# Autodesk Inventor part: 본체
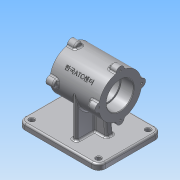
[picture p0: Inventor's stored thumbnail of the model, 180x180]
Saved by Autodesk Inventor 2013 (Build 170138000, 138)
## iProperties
Created: 2015-12
Part Number: 본체
Material: 알루미늄 6061
Document SubType Name: Modeling
Designer: Administrator
Density: 2.71 g/cm^3
Mass: 1164.59 g
Surface Area: 814.915 cm^2
Volume: 429.737 cm^3
Author: Administrator
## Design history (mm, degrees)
sketch "스케치1"
  geometry: L1 (-80, 55)-(60, 55); L2 (60, 55)-(60, -55); L3 (60, -55)-(-80, -55); L4 (-80, -55)-(-80, 55); 2 further points
  constraints: 8 end point, 2 parallel, 1 horizontal, 1 horizontal alignment, 1 midpoint, 1 perpendicular
  dimensions: "d0" = 140 distance of L1.start L1.end; "d2" = 110 distance of L3.end L1.start; "d3" = 80 distance from line of L4 point (0, 0)
extrude "돌출1" new body sketch "스케치1" distance "d4" = 10; taper "d5" = 0 deg
sketch "스케치5"
  geometry: L1 (-37, 80)-(-37, 0); L2 (37, 80)-(37, 0); L3 (-37, 80)-(37, 80); L4 (-37, 0)-(37, 0); A1 r 37 centre (0, 80) between (-37, 80) and (37, 80); 1 further point
  constraints: 8 end point, 2 parallel, 2 point on circle, 2 tangent, 1 centre point, 1 perpendicular, 1 vertical, 1 vertical alignment
  dimensions: "d30" = 74 diameter of A1; "d32" = 80 distance of point (0, 0) A1.centre
extrude "돌출4" join sketch "스케치5" stored distance "d33" = 85; taper "d34" = 0 deg
extrude "돌출5" join sketch "스케치5" stored distance "d35" = 8; taper "d36" = 0 deg
node "작업 평면2"
sketch "스케치7"
  geometry: L1 (80, 10)-(-60, 10) reference; L2 (-25, 10)-(-16.405, 80); L3 (-16.405, 80)-(16.405, 80); L4 (16.405, 80)-(25, 10); L5 (-60, 0)-(80, 0) reference; L6 (-25, 10)-(25, 10); 1 further point
  constraints: 8 end point, 2 point on line, 1 collinear, 1 parallel
  dimensions: "d40" = 25 horizontal distance of point (0, 0) L2.start; "d41" = 50 distance of L4.end L2.start; "d42" = 97 deg angle of L2 L1; "d43" = 97 deg angle of L4 L1; "d44" = 80 distance between parallel lines of L5 L3
extrude "돌출6" join sketch "스케치7" stored distance "d45" = 12; taper "d46" = 0 deg
sketch "스케치9"
  geometry: L1 (-80, 55)-(60, 55) reference; L2 (60, 55)-(60, -55) reference; L3 (60, -55)-(-80, -55) reference; L4 (-80, -55)-(-80, 55) reference; 5 further points
  constraints: 2 horizontal alignment, 2 vertical alignment
  dimensions: "d54" = 116 distance of point (48, 43) point (-68, 43); "d56" = 12 distance from line of L1 point (-68, 43); "d57" = 12 distance from line of point (-68, 43) L4; "d58" = 86 distance of point (-68, -43) point (-68, 43)
hole "구멍1" sketch "스케치9" at (-68, 43), (48, 43), (48, -43), (-68, -43) diameter "d59" = 8; stored, may be unused: countersink angle "d63" = 90 deg, drill point angle "d65" = 118 deg; dims "d60" = 6, "d61" = 4, "d62" = 2, "d64" = 8
fillet "모깎기1" dims "d66" = 12
node "작업 평면4"
sketch "스케치12"
  geometry: L1 (-23.753, 109.765)-(23.753, 109.765); L2 (23.753, 109.765)-(23.753, 102.561); L3 (23.753, 102.561)-(-23.753, 102.561); L4 (-23.753, 102.561)-(-23.753, 109.765); L5 (-42.5, 117)-(-42.5, 43) reference; 4 further points
  constraints: 2 midpoint, 1 horizontal alignment, 1 vertical alignment, 2 other
  dimensions: "d71" = 42.5 distance from line of point (0, 106.163) L5; "d72" = 106.163 distance of point (0, 0) point (0, 106.163)
feature "엠보싱1" sketch "스케치12" dims "d73" = 0.5, "d74" = 0
sketch "스케치18"
  geometry: L1 (-17.479, 105.93)-(-20.955, 105.93) reference; L2 (-20.955, 105.93)-(-20.955, 105.609) reference; L3 (-20.955, 105.609)-(-18.016, 105.609) reference; L4 (-18.016, 105.609)-(-18.016, 104.574) reference; L5 (-18.016, 104.574)-(-20.638, 104.574) reference; L6 (-20.638, 104.574)-(-20.638, 104.237) reference; L7 (-20.638, 104.237)-(-18.016, 104.237) reference; L8 (-18.016, 104.237)-(-18.016, 103.028) reference; L9 (-17.479, 102.651)-(-17.479, 105.93) reference; L10 (-11.764, 105.248)-(-13.001, 105.248) reference; L11 (-13.001, 105.248)-(-13.001, 106.527) reference; L12 (-13.001, 106.527)-(-13.449, 106.527) reference; L13 (-13.547, 106.328)-(-13.547, 102.721) reference; L14 (-13.547, 102.721)-(-13.001, 102.721) reference; L15 (-13.001, 102.721)-(-13.001, 104.943) reference; L16 (-13.001, 104.943)-(-11.764, 104.943) reference; L17 (-11.764, 104.943)-(-11.764, 105.248) reference; L18 (-10.404, 106.368)-(-10.885, 106.368) reference; L19 (0.586, 101.567)-(0.586, 105.784) reference; L20 (0.586, 105.784)-(2.45, 105.784) reference; L21 (2.45, 105.784)-(2.45, 106.138) reference; L22 (2.45, 106.138)-(-1.832, 106.138) reference; L23 (-1.832, 106.138)-(-1.832, 105.784) reference; L24 (-1.832, 105.784)-(0.041, 105.784) reference; L25 (0.041, 105.784)-(0.041, 101.567) reference; L26 (0.041, 101.567)-(0.586, 101.567) reference; L27 (5.853, 106.138)-(5.202, 106.138) reference; L28 (2.923, 101.567)-(3.501, 101.567) reference; L29 (4.168, 103.028)-(6.871, 103.028) reference; L30 (7.555, 101.567)-(8.133, 101.567) reference; L31 (22.624, 106.47)-(20.849, 106.47) reference; L32 (20.849, 106.47)-(20.849, 106.173) reference; L33 (20.849, 106.173)-(22.624, 106.173) reference; L34 (22.624, 106.173)-(22.624, 106.47) reference; L35 (18.073, 106.436)-(18.073, 104.622) reference; L36 (18.073, 104.622)-(16.73, 104.622) reference; L37 (16.73, 104.622)-(16.73, 104.268) reference; L38 (16.73, 104.268)-(18.073, 104.268) reference; L39 (18.073, 104.268)-(18.073, 102.651) reference; L40 (18.073, 102.651)-(18.643, 102.651) reference; L41 (18.643, 102.651)-(18.643, 106.657) reference; L42 (18.643, 106.657)-(18.277, 106.657) reference; L43 (22.478, 102.728)-(22.478, 101.739) reference; L44 (22.478, 101.739)-(17.813, 101.739) reference; L45 (17.813, 101.739)-(17.813, 101.368) reference; L46 (17.813, 101.368)-(23.031, 101.368) reference; L47 (23.031, 101.368)-(23.031, 102.933) reference; L48 (23.031, 102.933)-(22.608, 102.933) reference; L49 (24.057, 105.784)-(19.539, 105.784) reference; L50 (19.539, 105.784)-(19.539, 105.479) reference; L51 (19.539, 105.479)-(24.057, 105.479) reference; L52 (24.057, 105.479)-(24.057, 105.784) reference; L53 (15.973, 104.707)-(10.73, 104.707) reference; L54 (10.388, 106.161)-(14.955, 106.161) reference; L55 (14.955, 106.161)-(14.955, 106.482) reference; L56 (14.955, 106.482)-(9.81, 106.482) reference; L57 (10.136, 104.707)-(8.768, 104.707) reference; L58 (8.768, 104.707)-(8.768, 104.372) reference; L59 (8.768, 104.372)-(12.114, 104.372) reference; L60 (12.114, 104.372)-(12.114, 103.251) reference; L61 (12.114, 103.251)-(9.94, 103.251) reference; L62 (9.94, 103.251)-(9.94, 101.215) reference; L63 (9.94, 101.215)-(10.494, 101.215) reference; L64 (10.494, 101.215)-(10.494, 102.901) reference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; 60 further points
  constraints: 8 end point, 2 perpendicular, 1 parallel, 75 other
  dimensions: "d85" = 15 distance of L92.start L105.end; "d86" = 110 deg angle of L106 L109; "d87" = 7 distance between parallel lines of L109 L107
revolve "회전1" sketch "스케치18" stored, may be unused: angle "d88" = 90 deg
sketch "스케치19"
  geometry: C1 r 37 at (-80, 0); A1 r 37 centre (-80, 0) between (-43.662, 6.969) and (-73.031, 36.338) reference; A2 r 7 centre (-43, 0) between (-43.662, -6.969) and (-43.662, 6.969) reference; A3 r 37 centre (-80, 0) between (-73.031, -36.338) and (-43.662, -6.969) reference; A4 r 7 centre (-80, -37) between (-86.969, -36.338) and (-73.031, -36.338) reference; A5 r 37 centre (-80, 0) between (-116.338, -6.969) and (-86.969, -36.338) reference; A6 r 7 centre (-117, 0) between (-116.338, 6.969) and (-116.338, -6.969) reference; A7 r 37 centre (-80, 0) between (-86.969, 36.338) and (-116.338, 6.969) reference; A8 r 7 centre (-80, 37) between (-73.031, 36.338) and (-86.969, 36.338) reference; 5 further points
  constraints: 5 coincident, 1 centre point
  dimensions: "d92" = 74 diameter of C1
hole "구멍2" sketch "스케치19" at (-117, 0), (-80, 37), (-43, 0), (-80, -37) diameter "d93" = 3.242; stored, may be unused: countersink angle "d97" = 90 deg, drill point angle "d99" = 118 deg; dims "d94" = 9, "d95" = 4, "d96" = 2, "d98" = 11
sketch "스케치20"
  geometry: A1 r 37 centre (80, 0) between (116.338, 6.969) and (86.969, 36.338) reference; A2 r 37 centre (80, 0) between (80, 37) and (117, 0); 3 further points
  constraints: 4 point on circle, 2 horizontal alignment, 2 vertical alignment, 1 centre point, 1 coincident
  dimensions: "d100" = 74 diameter of A2
hole "구멍3" sketch "스케치20" at (80, 37), (117, 0), (43, 0), (80, -37) diameter "d101" = 3.242; stored, may be unused: countersink angle "d105" = 90 deg, drill point angle "d107" = 118 deg; dims "d102" = 9, "d103" = 4, "d104" = 2, "d106" = 11
sketch "스케치21"
  geometry: C1 r 1.621 at (-43, 0) reference; C2 r 1.621 at (-80, 37) reference; C3 r 1.621 at (-117, 0) reference; C4 r 1.621 at (-80, -37) reference; C5 r 23.5 at (-80, 0); A1 r 37 centre (-80, 0) between (-43.662, 6.969) and (-73.031, 36.338) reference; A2 r 7 centre (-43, 0) between (-43.662, -6.969) and (-43.662, 6.969) reference; A3 r 37 centre (-80, 0) between (-73.031, -36.338) and (-43.662, -6.969) reference; A4 r 7 centre (-80, -37) between (-86.969, -36.338) and (-73.031, -36.338) reference; A5 r 37 centre (-80, 0) between (-116.338, -6.969) and (-86.969, -36.338) reference; A6 r 7 centre (-117, 0) between (-116.338, 6.969) and (-116.338, -6.969) reference; A7 r 37 centre (-80, 0) between (-86.969, 36.338) and (-116.338, 6.969) reference; A8 r 7 centre (-80, 37) between (-73.031, 36.338) and (-86.969, 36.338) reference; 1 further point
  constraints: 1 centre point, 1 coincident
  dimensions: "d108" = 47 diameter of C5
extrude "돌출9" cut sketch "스케치21" distance "d109" = 22; taper "d110" = 0 deg
sketch "스케치22"
  geometry: C1 r 23.5 at (80, 0); A1 r 37 centre (80, 0) between (116.338, 6.969) and (86.969, 36.338) reference; 1 further point
  constraints: 1 centre point, 1 coincident
  dimensions: "d111" = 47 diameter of C1
extrude "돌출10" cut sketch "스케치22" distance "d112" = 22; taper "d113" = 0 deg
node "작업 평면6"
  node "작업 평면5"
sketch "스케치23"
  geometry: C1 r 23.5 at (0, 80) reference; C2 r 1.621 at (0, 43) reference; C3 r 1.621 at (37, 80) reference; C4 r 1.621 at (0, 117) reference; C5 r 1.621 at (-37, 80) reference; C6 r 21 at (0, 80); A1 r 37 centre (0, 80) between (6.969, 43.662) and (36.338, 73.031) reference; A2 r 7 centre (0, 43) between (-6.969, 43.662) and (6.969, 43.662) reference; A3 r 37 centre (0, 80) between (-36.338, 73.031) and (-6.969, 43.662) reference; A4 r 7 centre (-37, 80) between (-36.338, 86.969) and (-36.338, 73.031) reference; A5 r 37 centre (0, 80) between (-6.969, 116.338) and (-36.338, 86.969) reference; A6 r 7 centre (0, 117) between (6.969, 116.338) and (-6.969, 116.338) reference; A7 r 37 centre (0, 80) between (36.338, 86.969) and (6.969, 116.338) reference; A8 r 7 centre (37, 80) between (36.338, 73.031) and (36.338, 86.969) reference; 1 further point
  constraints: 1 centre point, 1 coincident
  dimensions: "d116" = 42 diameter of C6
extrude "돌출11" cut sketch "스케치23" distance "d117" = 41; taper "d118" = 0 deg
chamfer "모따기1" distance "d119" = 1; stored, may be unused: second distance "d120" = 2, angle "d121" = 45 deg
fillet "모깎기2" dims "d122" = 0.3
fillet "모깎기3" dims "d123" = 3
fillet "모깎기4" dims "d124" = 3
fillet "모깎기5" dims "d125" = 3
fillet "모깎기6" dims "d126" = 3
fillet "모깎기7" dims "d127" = 3
fillet "모깎기8" dims "d128" = 3
fillet "모깎기9" dims "d129" = 3
fillet "모깎기10" dims "d130" = 3
fillet "모깎기11" dims "d131" = 3
fillet "모깎기12" dims "d132" = 3
node "솔리드1"
pattern_circular "원형 패턴1" dims angle "d90" = 360 deg
mirror "대칭1"
node "투영된 루프6"
node "투영된 루프10"
node "투영된 루프11"
node "투영된 루프12"
node "투영된 루프13"
other parameters: "d37" = 42.5, "d70" = -37, "d114" = 42.5, "d115" = -22
